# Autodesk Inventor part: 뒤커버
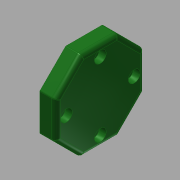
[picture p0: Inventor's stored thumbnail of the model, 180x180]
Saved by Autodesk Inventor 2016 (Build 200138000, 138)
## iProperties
Created: 2015-11
Part Number: 뒤커버
Material: 알루미늄 6061
Document SubType Name: Modeling
Designer: mduedu
Density: 1 g/cm^3
Appearance: 매끄러움 - 짙은 산림 녹색
Author: mduedu
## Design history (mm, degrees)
sketch "스케치5" dims "d66" = 60
  geometry: L1 (12.426, 30)-(30, 12.426); L2 (30, 12.426)-(30, -12.426); L3 (30, -12.426)-(12.426, -30); L4 (12.426, -30)-(-12.426, -30); L5 (-12.426, -30)-(-30, -12.426); L6 (-30, -12.426)-(-30, 12.426); L7 (-30, 12.426)-(-12.426, 30); L8 (-12.426, 30)-(12.426, 30); 4 further points
  constraints: 16 end point, 2 coincident, 2 vertical alignment, 1 midpoint, 19 other
extrude "돌출2" new body sketch "스케치5" distance "d67" = 11; taper "d68" = 0 deg
sketch "스케치6"
  geometry: C1 r 16 at (0, 0); 1 further point
  constraints: 1 centre point, 1 coincident
  dimensions: "d69" = 32 diameter of C1
extrude "돌출3" join sketch "스케치6" distance "d70" = 3; taper "d71" = 0 deg
hole "구멍5" diameter "d74" = 25; stored, may be unused: countersink angle "d78" = 90 deg, drill point angle "d80" = 0 deg; dims "d72" = 10, "d73" = 10, "d75" = 6, "d76" = 4, "d77" = 2, "d79" = 10
fillet "모깎기7" dims "d81" = 1
fillet "모깎기8" dims "d82" = 3
fillet "모깎기9" dims "d83" = 3
fillet "모깎기10" dims "d84" = 0.3
sketch "스케치7" dims "d85" = 46
  geometry: 3 further points
  constraints: 2 vertical alignment, 1 coincident, 2 other
hole "구멍6" sketch "스케치7" at (0, 23) diameter "d86" = 4.5; stored, may be unused: countersink angle "d90" = 90 deg, drill point angle "d92" = 0 deg; dims "d87" = 6, "d88" = 8, "d89" = 4.6, "d91" = 10
node "솔리드2"
pattern_circular "원형 패턴3" dims angle "d94" = 360 deg
